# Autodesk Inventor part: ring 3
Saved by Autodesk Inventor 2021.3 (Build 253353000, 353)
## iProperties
Created: 2022-02
Part Number: ring 3
Material: Generic
Document SubType Name: Modeling
Designer: Administrator
Density: 1 g/cm^3
Appearance: Default
Title: ring 3
Author: Administrator
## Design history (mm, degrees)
feature "Body1"
body "Solid1"
